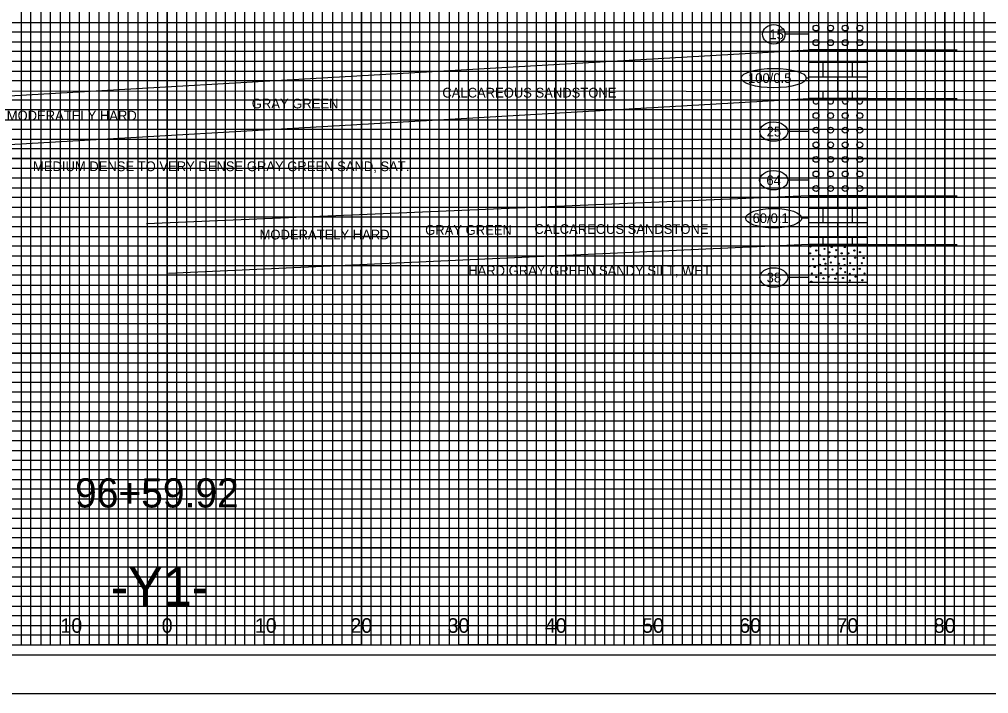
# Model space of a CAD drawing. Extents: x -13 to 886, y -5 to 434.
# Drawn here: x 707.1 to 806.7, y 195.9 to 265.2 of the extents above; entities that cross this region are included whole.
import ezdxf

# ---------------------------------------------------------------- set-up
doc = ezdxf.new("R2010")
doc.units = 0
for name, color, linetype in [('Prop Road Sect_ Boring - Material (Outline)', 7, 'Continuous'), ('Prop Road Sect_ Boring - Peripheral (SPT Oval + Leader)', 7, 'Continuous'), ('Prop Road Sect_ Boring - Peripheral (SPT Tx)', 7, 'Continuous'), ('Prop Road Sect_ Material - Contact (General - Minor)', 7, 'Continuous'), ('Prop Road Sect_ Material - Tx (Composite Desc)', 7, 'Continuous'), ('Prop XS Alignment Label', 7, 'Continuous'), ('Prop XS Offset Labels', 7, 'Continuous'), ('Prop XS Station Labels', 7, 'Continuous'), ('Sheet Cross Section CELL', 7, 'Continuous'), ('Sheet Cross Section Grid Major CELL', 7, 'Continuous'), ('Sheet Cross Section Grid Middle CELL', 7, 'Continuous'), ('Sheet Cross Section Grid Minor 1 CELL', 7, 'Continuous'), ('Sheet Cross Section Grid Minor 2 CELL', 7, 'Continuous'), ('Sheet Cutting Line CELL', 7, 'Continuous'), ('Sheet DOT Grid CELL', 7, 'Continuous'), ('Sheet Plot Border Inside CELL', 7, 'Continuous'), ('Sheet Plot Border Outside CELL', 7, 'Continuous')]:
    doc.layers.add(name, color=color, linetype=linetype)

msp = doc.modelspace()

# ---------------------------------------------------------------- linework, layer by layer
at = {"layer": 'Prop Road Sect_ Boring - Material (Outline)'}
for p, q in [((791.237, 260.823), (791.237, 262.077)), ((788.243, 260.823), (794.237, 260.823)), ((789.737, 259.324), (789.737, 260.823)), ((792.737, 259.324), (792.737, 260.823)), ((794.24, 260.823), (794.243, 260.823)), ((788.243, 259.324), (794.237, 259.324)), ((791.237, 257.826), (791.237, 259.324)), ((794.24, 259.324), (794.243, 259.324)), ((788.243, 257.826), (794.237, 257.826)), ((789.737, 257.077), (789.737, 257.826)), ((792.737, 257.077), (792.737, 257.826)), ((794.24, 257.826), (794.243, 257.826)), ((791.237, 245.823), (791.237, 247.077)), ((788.243, 245.823), (794.237, 245.823)), ((789.737, 244.324), (789.737, 245.823)), ((792.737, 244.324), (792.737, 245.823)), ((794.24, 245.823), (794.243, 245.823)), ((788.243, 244.324), (794.237, 244.324)), ((791.237, 242.826), (791.237, 244.324)), ((794.24, 244.324), (794.243, 244.324)), ((788.243, 242.826), (794.237, 242.826)), ((789.737, 242.077), (789.737, 242.826)), ((792.737, 242.077), (792.737, 242.826)), ((794.24, 242.826), (794.243, 242.826))]:
    msp.add_line(p, q, dxfattribs=at)
for points in [[(788.243, 277.077), (794.243, 277.077), (794.243, 262.077), (788.243, 262.077)], [(788.243, 262.077), (794.243, 262.077), (794.243, 257.077), (788.243, 257.077)], [(788.243, 257.077), (794.243, 257.077), (794.243, 247.077), (788.243, 247.077)], [(788.243, 247.077), (794.243, 247.077), (794.243, 242.077), (788.243, 242.077)], [(788.243, 242.077), (794.243, 242.077), (794.243, 238.177), (788.243, 238.177)]]:
    msp.add_lwpolyline(points, close=True, dxfattribs=at)
for centre, radius in [((788.99, 264.322), 0.3), ((790.49, 264.322), 0.3), ((791.99, 264.322), 0.3), ((793.49, 264.322), 0.3), ((788.99, 262.822), 0.3), ((790.49, 262.822), 0.3), ((791.99, 262.822), 0.3), ((793.49, 262.822), 0.3), ((788.99, 255.319), 0.3), ((790.49, 255.319), 0.3), ((791.99, 255.319), 0.3), ((793.49, 255.319), 0.3), ((788.99, 253.819), 0.3), ((790.49, 253.819), 0.3), ((791.99, 253.819), 0.3), ((793.49, 253.819), 0.3), ((788.99, 252.322), 0.3), ((790.49, 252.322), 0.3), ((791.99, 252.322), 0.3), ((793.49, 252.322), 0.3), ((788.99, 250.822), 0.3), ((790.49, 250.822), 0.3), ((791.99, 250.822), 0.3), ((793.49, 250.822), 0.3), ((788.99, 249.322), 0.3), ((790.49, 249.322), 0.3), ((791.99, 249.322), 0.3), ((793.49, 249.322), 0.3), ((788.99, 247.822), 0.3), ((790.49, 247.822), 0.3), ((791.99, 247.822), 0.3), ((793.49, 247.822), 0.3), ((788.417, 241.863), 0.06), ((789.017, 241.455), 0.06), ((789.617, 241.971), 0.06), ((789.863, 241.617), 0.06), ((790.352, 241.263), 0.06), ((790.598, 241.809), 0.06), ((791.06, 241.482), 0.06), ((791.96, 241.809), 0.06), ((792.938, 241.455), 0.06), ((793.511, 241.29), 0.06), ((788.363, 241.155), 0.06), ((788.69, 240.555), 0.06), ((789.371, 240.963), 0.06), ((789.806, 240.555), 0.06), ((790.298, 240.801), 0.06), ((790.514, 240.228), 0.06), ((790.979, 240.801), 0.06), ((791.633, 241.155), 0.06), ((791.876, 240.582), 0.06), ((792.314, 241.155), 0.06), ((793.022, 240.717), 0.06), ((793.892, 240.69), 0.06), ((788.309, 239.847), 0.06), ((788.855, 239.766), 0.06), ((789.425, 239.982), 0.06), ((789.971, 240.093), 0.06), ((789.971, 239.574), 0.06), ((790.679, 239.493), 0.06), ((791.333, 240.093), 0.06), ((791.522, 239.601), 0.06), ((791.93, 239.955), 0.06), ((791.987, 239.22), 0.06), ((792.503, 240.147), 0.06), ((792.857, 239.52), 0.06), ((793.484, 239.574), 0.06), ((793.703, 240.147), 0.06), ((788.501, 238.249), 0.06), ((788.555, 239.085), 0.06), ((789.017, 238.731), 0.06), ((789.482, 239.139), 0.06), ((789.752, 238.585), 0.06), ((790.271, 238.731), 0.06), ((790.979, 238.566), 0.06), ((791.141, 239.085), 0.06), ((791.768, 238.62), 0.06), ((792.476, 239.058), 0.06), ((792.476, 238.377), 0.06), ((793.076, 238.758), 0.06), ((793.757, 238.404), 0.06), ((793.968, 239.096), 0.06)]:
    msp.add_circle(centre, radius, dxfattribs=at)
for centre, radius, start, end in [((788.99, 256.819), 0.3, 120.80794, 59.19206), ((790.49, 256.819), 0.3, 120.80794, 59.19206), ((791.99, 256.819), 0.3, 120.80794, 59.19206), ((793.49, 256.819), 0.3, 120.80794, 59.19206), ((788.99, 242.133), 0.06, 251.64702, 288.35298), ((791.522, 242.079), 0.06, 182.81635, 357.18365), ((792.995, 242.025), 0.06, 121.6941, 58.3059), ((793.784, 242.133), 0.06, 251.64702, 288.35298)]:
    msp.add_arc(centre, radius, start, end, dxfattribs=at)
at = {"layer": 'Prop Road Sect_ Boring - Peripheral (SPT Oval + Leader)'}
for p, q in [((788.243, 263.677), (785.792, 263.677)), ((788.243, 259.176), (787.989, 259.176)), ((788.243, 253.677), (786.075, 253.677)), ((788.243, 248.677), (786.099, 248.677)), ((788.243, 244.777), (787.524, 244.777)), ((788.243, 238.677), (786.075, 238.677))]:
    msp.add_line(p, q, dxfattribs=at)
for centre, major_axis, ratio in [((784.643, 263.677), (1.149, 0), 0.870459), ((784.643, 259.176), (3.346, 0), 0.298894), ((784.643, 253.677), (1.432, 0), 0.698186), ((784.643, 248.677), (1.456, 0), 0.686858), ((784.643, 244.777), (2.881, 0), 0.347089), ((784.643, 238.677), (1.432, 0), 0.698186)]:
    msp.add_ellipse(centre, major_axis=major_axis, ratio=ratio, dxfattribs=at)
at = {"layer": 'Prop Road Sect_ Material - Contact (General - Minor)'}
for p, q in [((691.243, 256.49), (788.243, 262.077)), ((794.243, 262.077), (803.525, 262.077)), ((691.243, 251.49), (788.243, 257.077)), ((794.243, 257.077), (803.525, 257.077)), ((788.243, 247.077), (720.128, 244.197)), ((794.243, 247.077), (803.525, 247.077)), ((788.243, 242.077), (722.405, 239.074)), ((794.243, 242.077), (803.525, 242.077))]:
    msp.add_line(p, q, dxfattribs=at)
at = {"layer": 'Sheet Cross Section CELL'}
msp.add_lwpolyline([(882.243, 410.903), (562.243, 410.903), (562.243, 200.903), (882.243, 200.903)], close=True, dxfattribs=at)
at = {"layer": 'Sheet Cross Section Grid Major CELL'}
for p, q in [((712.243, 200.903), (712.243, 410.903)), ((722.243, 410.903), (722.243, 200.903)), ((732.243, 200.903), (732.243, 410.903)), ((742.243, 410.903), (742.243, 200.903)), ((752.243, 200.903), (752.243, 410.903)), ((762.243, 410.903), (762.243, 200.903)), ((772.243, 200.903), (772.243, 410.903)), ((782.243, 410.903), (782.243, 200.903)), ((792.243, 200.903), (792.243, 410.903)), ((802.243, 410.903), (802.243, 200.903)), ((722.243, 200.903), (712.243, 200.903)), ((742.243, 200.903), (732.243, 200.903)), ((762.243, 200.903), (752.243, 200.903)), ((782.243, 200.903), (772.243, 200.903)), ((802.243, 200.903), (792.243, 200.903))]:
    msp.add_line(p, q, dxfattribs=at)
for points in [[(562.243, 260.903), (882.243, 260.903), (882.243, 250.903), (562.243, 250.903)], [(562.243, 240.903), (882.243, 240.903), (882.243, 230.903), (562.243, 230.903)], [(562.243, 220.903), (882.243, 220.903), (882.243, 210.903), (562.243, 210.903)]]:
    msp.add_lwpolyline(points, dxfattribs=at)
at = {"layer": 'Sheet Cross Section Grid Middle CELL'}
for points in [[(707.243, 410.903), (707.243, 200.903), (717.243, 200.903), (717.243, 410.903)], [(727.243, 410.903), (727.243, 200.903), (737.243, 200.903), (737.243, 410.903)], [(747.243, 410.903), (747.243, 200.903), (757.243, 200.903), (757.243, 410.903)], [(767.243, 410.903), (767.243, 200.903), (777.243, 200.903), (777.243, 410.903)], [(787.243, 410.903), (787.243, 200.903), (797.243, 200.903), (797.243, 410.903)], [(562.243, 245.903), (882.243, 245.903), (882.243, 255.903), (562.243, 255.903)], [(562.243, 225.903), (882.243, 225.903), (882.243, 235.903), (562.243, 235.903)], [(562.243, 205.903), (882.243, 205.903), (882.243, 215.903), (562.243, 215.903)]]:
    msp.add_lwpolyline(points, dxfattribs=at)
at = {"layer": 'Sheet Cross Section Grid Minor 1 CELL'}
for points in [[(562.243, 264.903), (882.243, 264.903), (882.243, 263.903), (562.243, 263.903)], [(562.243, 262.903), (882.243, 262.903), (882.243, 261.903), (562.243, 261.903)], [(562.243, 259.903), (882.243, 259.903), (882.243, 258.903), (562.243, 258.903)], [(562.243, 257.893), (882.313, 257.813), (882.243, 256.903), (562.243, 256.903)], [(562.243, 254.903), (882.243, 254.903), (882.243, 253.903), (562.243, 253.903)], [(562.243, 252.903), (882.243, 252.903), (882.243, 251.903), (562.243, 251.903)], [(562.243, 249.903), (882.243, 249.903), (882.243, 248.903), (562.243, 248.903)], [(562.243, 247.903), (882.243, 247.903), (882.243, 246.903), (562.243, 246.903)], [(562.243, 244.903), (882.243, 244.903), (882.243, 243.903), (562.243, 243.903)], [(562.243, 242.903), (882.243, 242.903), (882.243, 241.903), (562.243, 241.903)], [(562.243, 239.903), (882.243, 239.903), (882.243, 238.903), (562.243, 238.903)], [(562.243, 237.903), (882.243, 237.903), (882.243, 236.903), (562.243, 236.903)], [(562.243, 234.903), (882.243, 234.903), (882.243, 233.903), (562.243, 233.903)], [(562.243, 232.903), (882.243, 232.903), (882.243, 231.903), (562.243, 231.903)], [(562.243, 229.903), (882.243, 229.903), (882.243, 228.903), (562.243, 228.903)], [(562.243, 227.903), (882.243, 227.903), (882.243, 226.903), (562.243, 226.903)], [(562.243, 224.903), (882.243, 224.903), (882.243, 223.903), (562.243, 223.903)], [(562.243, 222.903), (882.243, 222.903), (882.243, 221.903), (562.243, 221.903)], [(562.243, 219.903), (882.243, 219.903), (882.243, 218.903), (562.243, 218.903)], [(562.243, 217.903), (882.243, 217.903), (882.243, 216.903), (562.243, 216.903)], [(562.243, 214.903), (882.243, 214.903), (882.243, 213.903), (562.243, 213.903)], [(562.243, 212.903), (882.243, 212.903), (882.243, 211.903), (562.243, 211.903)], [(562.243, 209.903), (882.243, 209.903), (882.243, 208.903), (562.243, 208.903)], [(562.243, 207.903), (882.243, 207.903), (882.243, 206.903), (562.243, 206.903)], [(562.243, 204.903), (882.243, 204.903), (882.243, 203.903), (562.243, 203.903)], [(562.243, 202.903), (882.243, 202.903), (882.243, 201.903), (562.243, 201.903)]]:
    msp.add_lwpolyline(points, dxfattribs=at)
at = {"layer": 'Sheet Cross Section Grid Minor 2 CELL'}
for points in [[(707.243, 200.903), (708.243, 200.903), (708.243, 410.903), (709.243, 410.903), (709.243, 200.903)], [(709.243, 200.903), (710.243, 200.903), (710.243, 410.903), (711.243, 410.903), (711.243, 200.903)], [(712.243, 200.903), (713.243, 200.903), (713.243, 410.903), (714.243, 410.903), (714.243, 200.903)], [(714.243, 200.903), (715.243, 200.903), (715.243, 410.903), (716.243, 410.903), (716.243, 200.903)], [(717.243, 200.903), (718.243, 200.903), (718.243, 410.903), (719.243, 410.903), (719.243, 200.903)], [(719.243, 200.903), (720.243, 200.903), (720.243, 410.903), (721.243, 410.903), (721.243, 200.903)], [(722.243, 200.903), (723.243, 200.903), (723.243, 410.903), (724.243, 410.903), (724.243, 200.903)], [(724.243, 200.903), (725.243, 200.903), (725.243, 410.903), (726.243, 410.903), (726.243, 200.903)], [(727.243, 200.903), (728.243, 200.903), (728.243, 410.903), (729.243, 410.903), (729.243, 200.903)], [(729.243, 200.903), (730.243, 200.903), (730.243, 410.903), (731.243, 410.903), (731.243, 200.903)], [(732.243, 200.903), (733.243, 200.903), (733.243, 410.903), (734.243, 410.903), (734.243, 200.903)], [(734.243, 200.903), (735.243, 200.903), (735.243, 410.903), (736.243, 410.903), (736.243, 200.903)], [(737.243, 200.903), (738.243, 200.903), (738.243, 410.903), (739.243, 410.903), (739.243, 200.903)], [(739.243, 200.903), (740.243, 200.903), (740.243, 410.903), (741.243, 410.903), (741.243, 200.903)], [(742.243, 200.903), (743.243, 200.903), (743.243, 410.903), (744.243, 410.903), (744.243, 200.903)], [(744.243, 200.903), (745.243, 200.903), (745.243, 410.903), (746.243, 410.903), (746.243, 200.903)], [(747.243, 200.903), (748.243, 200.903), (748.243, 410.903), (749.243, 410.903), (749.243, 200.903)], [(749.243, 200.903), (750.243, 200.903), (750.243, 410.903), (751.243, 410.903), (751.243, 200.903)], [(752.243, 200.903), (753.243, 200.903), (753.243, 410.903), (754.243, 410.903), (754.243, 200.903)], [(754.243, 200.903), (755.243, 200.903), (755.243, 410.903), (756.243, 410.903), (756.243, 200.903)], [(757.243, 200.903), (758.243, 200.903), (758.243, 410.903), (759.243, 410.903), (759.243, 200.903)], [(759.243, 200.903), (760.243, 200.903), (760.243, 410.903), (761.243, 410.903), (761.243, 200.903)], [(762.243, 200.903), (763.243, 200.903), (763.243, 410.903), (764.243, 410.903), (764.243, 200.903)], [(764.243, 200.903), (765.243, 200.903), (765.243, 410.903), (766.243, 410.903), (766.243, 200.903)], [(767.243, 200.903), (768.243, 200.903), (768.243, 410.903), (769.243, 410.903), (769.243, 200.903)], [(769.243, 200.903), (770.243, 200.903), (770.243, 410.903), (771.243, 410.903), (771.243, 200.903)], [(772.243, 200.903), (773.243, 200.903), (773.243, 410.903), (774.243, 410.903), (774.243, 200.903)], [(774.243, 200.903), (775.243, 200.903), (775.243, 410.903), (776.243, 410.903), (776.243, 200.903)], [(777.243, 200.903), (778.243, 200.903), (778.243, 410.903), (779.243, 410.903), (779.243, 200.903)], [(779.243, 200.903), (780.243, 200.903), (780.243, 410.903), (781.243, 410.903), (781.243, 200.903)], [(782.243, 200.903), (783.243, 200.903), (783.243, 410.903), (784.243, 410.903), (784.243, 200.903)], [(784.243, 200.903), (785.243, 200.903), (785.243, 410.903), (786.243, 410.903), (786.243, 200.903)], [(787.243, 200.903), (788.243, 200.903), (788.243, 410.903), (789.243, 410.903), (789.243, 200.903)], [(789.243, 200.903), (790.243, 200.903), (790.243, 410.903), (791.243, 410.903), (791.243, 200.903)], [(792.243, 200.903), (793.243, 200.903), (793.243, 410.903), (794.243, 410.903), (794.243, 200.903)], [(794.243, 200.903), (795.243, 200.903), (795.243, 410.903), (796.243, 410.903), (796.243, 200.903)], [(797.243, 200.903), (798.243, 200.903), (798.243, 410.903), (799.243, 410.903), (799.243, 200.903)], [(799.243, 200.903), (800.243, 200.903), (800.243, 410.903), (801.243, 410.903), (801.243, 200.903)], [(802.243, 200.903), (803.243, 200.903), (803.243, 410.903), (804.243, 410.903), (804.243, 200.903)], [(804.243, 200.903), (805.243, 200.903), (805.243, 410.903), (806.243, 410.903), (806.243, 200.903)]]:
    msp.add_lwpolyline(points, dxfattribs=at)
at = {"layer": 'Sheet Cutting Line CELL'}
msp.add_line((548.843, 195.903), (885.543, 195.903), dxfattribs=at)
at = {"layer": 'Sheet DOT Grid CELL'}
for p, q in [((712.243, 200.903), (712.243, 410.903)), ((722.243, 200.903), (722.243, 410.903)), ((732.243, 200.903), (732.243, 410.903)), ((742.243, 200.903), (742.243, 410.903)), ((752.243, 200.903), (752.243, 410.903)), ((762.243, 200.903), (762.243, 410.903)), ((772.243, 200.903), (772.243, 410.903)), ((782.243, 200.903), (782.243, 410.903)), ((792.243, 200.903), (792.243, 410.903)), ((802.243, 200.903), (802.243, 410.903)), ((562.243, 260.903), (882.243, 260.903)), ((562.243, 250.903), (882.243, 250.903)), ((562.243, 240.903), (882.243, 240.903)), ((562.243, 230.903), (882.243, 230.903)), ((562.243, 220.903), (882.243, 220.903)), ((562.243, 210.903), (882.243, 210.903))]:
    msp.add_line(p, q, dxfattribs=at)
at = {"layer": 'Sheet Plot Border Inside CELL'}
msp.add_lwpolyline([(551.443, 199.903), (884.643, 199.903), (884.643, 410.903), (551.443, 410.903)], close=True, dxfattribs=at)
at = {"layer": 'Sheet Plot Border Outside CELL'}
msp.add_lwpolyline([(548.843, 195.903), (885.543, 195.903), (885.543, 414.903), (548.843, 414.903)], close=True, dxfattribs=at)

# ---------------------------------------------------------------- texts
at = {"layer": 'Prop Road Sect_ Boring - Peripheral (SPT Tx)'}
for s, p in [('15', (784.194, 263.177)), ('100/0.5', (781.997, 258.676)), ('25', (783.911, 253.177)), ('64', (783.887, 248.177)), ('60/0.1', (782.462, 244.277)), ('38', (783.911, 238.177))]:
    msp.add_text(s, height=1, dxfattribs=at).set_placement(p)
at = {"layer": 'Prop Road Sect_ Material - Tx (Composite Desc)'}
for s, p in [('CALCAREOUS SANDSTONE', (750.554, 257.177)), ('GRAY GREEN', (730.954, 256.062)), ('MODERATELY HARD', (705.75, 254.829)), ('MEDIUM DENSE TO VERY DENSE GRAY GREEN SAND, SAT.', (708.452, 249.612)), ('MODERATELY HARD', (731.754, 242.592)), ('GRAY GREEN', (748.788, 243.066)), ('CALCAREOUS SANDSTONE', (760.028, 243.161)), ('HARD GRAY GREEN SANDY SILT, WET', (753.22, 238.892))]:
    msp.add_text(s, height=1, dxfattribs=at).set_placement(p)
at = {"layer": 'Prop XS Alignment Label'}
msp.add_text('-Y1-', height=4, dxfattribs=at).set_placement((716.456, 204.903))
at = {"layer": 'Prop XS Offset Labels'}
for s, p in [('10', (711.28, 202.153)), ('0', (721.694, 202.153)), ('0', (721.694, 202.153)), ('10', (731.28, 202.153)), ('20', (741.101, 202.153)), ('30', (751.101, 202.153)), ('40', (761.101, 202.153)), ('50', (771.101, 202.153)), ('60', (781.101, 202.153)), ('70', (791.101, 202.153)), ('80', (801.101, 202.153))]:
    msp.add_text(s, height=1.5, dxfattribs=at).set_placement(p)
at = {"layer": 'Prop XS Station Labels'}
msp.add_text('96+59.92', height=3, dxfattribs=at).set_placement((712.773, 215.036))

doc.saveas('drawing.dxf')
